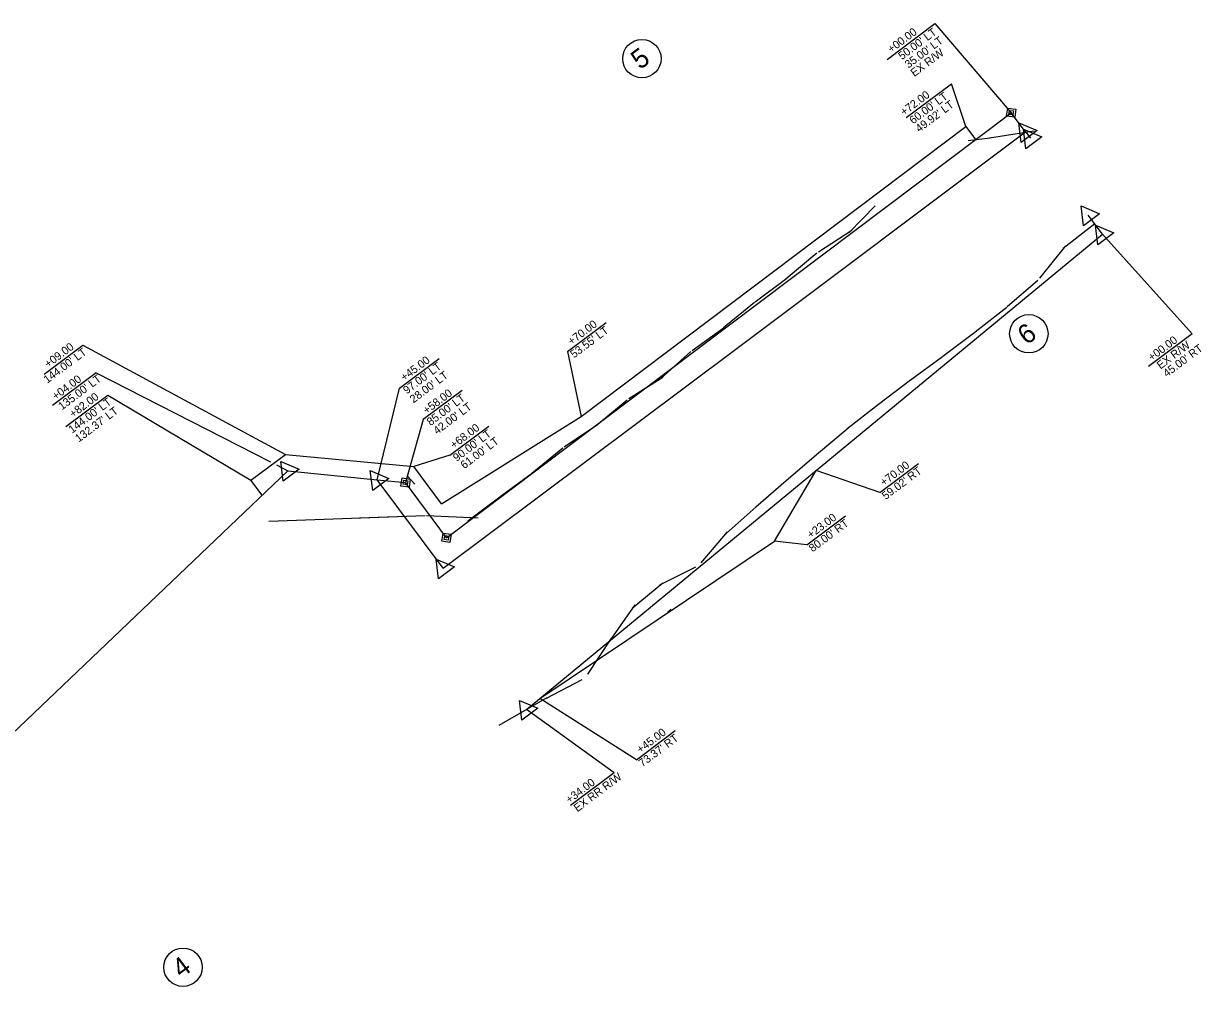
# Model space of a CAD drawing. Extents: x 2187066 to 2190381, y 630308 to 634921.
# Drawn here: x 2187609 to 2188345, y 630712 to 631314 of the extents above; entities that cross this region are included whole.
import ezdxf

# ---------------------------------------------------------------- set-up
doc = ezdxf.new("R2010")
doc.units = 0
for name, color, linetype in [('Default', 7, 'Continuous'), ('Old_Level_1', 7, 'Continuous'), ('Prop Dimension', 7, 'Continuous'), ('Prop Dimension Text', 7, 'Continuous'), ('Prop Guardrail', 7, 'Continuous'), ('Prop Guardrail Anchor Unit CELL', 7, 'Continuous'), ('Prop Horizontal Alignment', 7, 'Continuous'), ('Prop Horizontal Alignment Curve and Spiral Data', 7, 'Continuous'), ('Prop Horizontal Alignment Tick Large', 7, 'Continuous'), ('Prop Horizontal Alignment Tick Small', 7, 'Continuous'), ('Prop Lane Lines', 7, 'Continuous'), ('Prop Paved Shoulder', 7, 'Continuous'), ('Raster_Level_3', 7, 'Continuous'), ('Scratch_Level_3', 7, 'Continuous')]:
    doc.layers.add(name, color=color, linetype=linetype)

msp = doc.modelspace()

# ---------------------------------------------------------------- linework, layer by layer
at = {"layer": 'Default'}
msp.add_line((2187853.68, 631025.69), (2187849, 631030.96), dxfattribs=at)
at = {"layer": 'Old_Level_1'}
for p, q in [((2188053.44, 631109.47), (2188235.45, 631245.82)), ((2188235.45, 631245.82), (2188238.45, 631241.82)), ((2188283.44, 631181.81), (2188274.44, 631193.81)), ((2187923.54, 630884.86), (2188283.44, 631181.81)), ((2187871.43, 630973.13), (2188053.44, 631109.47)), ((2187467.92, 630741.67), (2187774.33, 631034.12)), ((2187774.33, 631034.12), (2187830.23, 631028.48)), ((2187871.43, 630973.13), (2187830.23, 631028.48))]:
    msp.add_line(p, q, dxfattribs=at)
at = {"layer": 'Prop Dimension Text'}
for p, q in [((2188226.45, 631257.82), (2188226.45, 631257.82)), ((2187847.95, 631026.69), (2187847.95, 631026.69)), ((2187873.51, 630992.22), (2187873.51, 630992.22))]:
    msp.add_line(p, q, dxfattribs=at)
for points in [[(2188224.29, 631260.7), (2188229.33, 631259.98), (2188228.61, 631254.94), (2188223.57, 631255.66)], [(2188225.37, 631259.26), (2188227.89, 631258.9), (2188227.53, 631256.38), (2188225.01, 631256.74)], [(2187850.1, 631023.81), (2187845.06, 631024.53), (2187845.79, 631029.57), (2187850.83, 631028.85)], [(2187849.02, 631025.25), (2187846.51, 631025.61), (2187846.87, 631028.13), (2187849.39, 631027.77)], [(2187871.36, 630995.1), (2187876.4, 630994.38), (2187875.67, 630989.34), (2187870.63, 630990.06)], [(2187872.43, 630993.66), (2187874.95, 630993.3), (2187874.59, 630990.78), (2187872.07, 630991.14)]]:
    msp.add_lwpolyline(points, close=True, dxfattribs=at)
at = {"layer": 'Prop Guardrail'}
for p, q in [((2187883.24, 631084.23), (2187858.96, 631066.02)), ((2187858.96, 631066.02), (2187847.95, 631026.69))]:
    msp.add_line(p, q, dxfattribs=at)
at = {"layer": 'Prop Guardrail Anchor Unit CELL'}
for p, q in [((2187873.56, 630992.15), (2188226.45, 631257.82)), ((2188235.45, 631245.82), (2188226.45, 631257.82)), ((2187830.23, 631028.48), (2187847.95, 631026.69)), ((2187873.56, 630992.15), (2187847.95, 631026.69))]:
    msp.add_line(p, q, dxfattribs=at)
at = {"layer": 'Prop Horizontal Alignment'}
for p, q in [((2188148.95, 631291.12), (2188178.81, 631313.5)), ((2188178.81, 631313.5), (2188226.45, 631257.82)), ((2188339.49, 631119.67), (2188283.44, 631181.81)), ((2188339.49, 631119.67), (2188312.17, 631099.18)), ((2187844.19, 631085.72), (2187868.88, 631104.23)), ((2187654.53, 631095.3), (2187627.2, 631074.81)), ((2187654.53, 631095.3), (2187763.63, 631039.59)), ((2187830.23, 631028.48), (2187844.19, 631085.72)), ((2187767.19, 631037.77), (2187774.33, 631034.12)), ((2187978.31, 630845.34), (2187923.54, 630884.86)), ((2187978.31, 630845.34), (2187950.98, 630824.86))]:
    msp.add_line(p, q, dxfattribs=at)
at = {"layer": 'Prop Horizontal Alignment Curve and Spiral Data'}
for p, q in [((2188212.97, 631242.14), (2188240.87, 631246.44)), ((2188199.47, 631240.44), (2188213.24, 631242.18)), ((2188125.15, 631183.04), (2188141.33, 631199.58)), ((2188258.95, 631173.09), (2188278.64, 631188.62)), ((2188105.97, 631170.86), (2188126.85, 631184.43)), ((2188244.33, 631154.44), (2188260.56, 631174.68)), ((2188085.87, 631154.17), (2188105.01, 631170.15)), ((2188066.34, 631139.7), (2188086.32, 631154.52)), ((2188224.01, 631136.67), (2188243.07, 631153.13)), ((2188046.69, 631123.51), (2188065.94, 631139.38)), ((2188203.85, 631120.87), (2188223.64, 631136.36)), ((2188027.01, 631109.17), (2188047.16, 631123.87)), ((2188183.74, 631105.58), (2188203.74, 631120.78)), ((2188007.41, 631091.65), (2188026.23, 631108.53)), ((2188163.25, 631090.68), (2188183.57, 631105.46)), ((2187987.49, 631079.23), (2188008.75, 631092.66)), ((2188143.42, 631075.61), (2188163.42, 631090.81)), ((2187967.06, 631062.45), (2187986.45, 631078.48)), ((2188123.76, 631060.18), (2188143.54, 631075.7)), ((2187947.02, 631048.95), (2187967.82, 631063.02)), ((2188104.69, 631044.19), (2188124.01, 631060.38)), ((2187926.8, 631032.56), (2187946.31, 631048.42)), ((2188085.68, 631027.86), (2188104.78, 631044.27)), ((2187906.97, 631017.95), (2187927.17, 631032.85)), ((2188066.87, 631011.51), (2188085.73, 631027.9)), ((2187886.84, 631002.75), (2187906.88, 631017.88)), ((2188048.28, 630994.97), (2188066.96, 631011.58)), ((2187762.54, 631002.64), (2187860.19, 631006.16)), ((2187819.14, 631004.68), (2187860.19, 631006.16)), ((2187860.99, 631006.16), (2187893.3, 631004.76)), ((2187860.99, 631006.16), (2187893.3, 631004.76)), ((2188032.58, 630976.52), (2188049.22, 630995.93)), ((2188006.94, 630962.84), (2188029.45, 630974.08)), ((2187989.56, 630948.29), (2188008.81, 630964.05)), ((2187976.38, 630928.8), (2187991.42, 630950.29)), ((2187961.94, 630907), (2187976.52, 630929.02)), ((2187935.93, 630892.08), (2187958.21, 630903.65)), ((2187936.33, 630892.3), (2187906.25, 630874.9))]:
    msp.add_line(p, q, dxfattribs=at)
at = {"layer": 'Prop Horizontal Alignment Tick Large'}
msp.add_line((2188011.86, 630945.95), (2188013.93, 630947.52), dxfattribs=at)
at = {"layer": 'Prop Horizontal Alignment Tick Small'}
for p, q in [((2188160.79, 631254.71), (2188189.05, 631275.9)), ((2188198.17, 631249.16), (2188189.05, 631275.9)), ((2187949.07, 631108.53), (2187973.36, 631126.74)), ((2187622.07, 631094.4), (2187646.35, 631112.61)), ((2187646.35, 631112.61), (2187772.94, 631044.33)), ((2187949.07, 631108.53), (2187957.72, 631067.96)), ((2187635.59, 631061.65), (2187661.92, 631081.39)), ((2187661.92, 631081.39), (2187751.33, 631028.13)), ((2187875.62, 631043.8), (2187899.9, 631062.01)), ((2187875.62, 631043.8), (2187853.09, 631036.72)), ((2188144.32, 631020.44), (2188104.56, 631034.22)), ((2188144.32, 631020.44), (2188168.6, 631038.64)), ((2188098.65, 630987.73), (2188122.93, 631005.94)), ((2188098.65, 630987.73), (2188078.43, 630990.09)), ((2187992.17, 630853.52), (2187931.95, 630891.81)), ((2187992.17, 630853.52), (2188016.45, 630871.73))]:
    msp.add_line(p, q, dxfattribs=at)
at = {"layer": 'Prop Lane Lines'}
for p, q in [((2187995.64, 631291.61), (2187995.64, 631291.61)), ((2188237.45, 631119.68), (2188237.45, 631119.68)), ((2187708.84, 630723.87), (2187708.84, 630723.87))]:
    msp.add_line(p, q, dxfattribs=at)
for centre in [(2187995.64, 631291.61), (2188237.45, 631119.68), (2187708.84, 630723.87)]:
    msp.add_circle(centre, 12, dxfattribs=at)
at = {"layer": 'Prop Paved Shoulder'}
msp.add_line((2188235.45, 631245.82), (2188235.45, 631245.82), dxfattribs=at)
msp.add_lwpolyline([(2188232.61, 631239.19), (2188231.13, 631251.58), (2188242.61, 631246.68)], close=True, dxfattribs=at)
at = {"layer": 'Raster_Level_3'}
for p, q in [((2188238.45, 631241.82), (2188238.45, 631241.82)), ((2188274.44, 631193.81), (2188274.44, 631193.81)), ((2188283.44, 631181.81), (2188283.44, 631181.81)), ((2187774.33, 631034.12), (2187774.33, 631034.12)), ((2187830.23, 631028.48), (2187830.23, 631028.48)), ((2187871.43, 630973.13), (2187871.43, 630973.13)), ((2187923.54, 630884.86), (2187923.54, 630884.86))]:
    msp.add_line(p, q, dxfattribs=at)
for points in [[(2188235.61, 631235.19), (2188234.13, 631247.58), (2188245.61, 631242.68)], [(2188271.6, 631187.18), (2188270.12, 631199.57), (2188281.6, 631194.68)], [(2188280.6, 631175.18), (2188279.12, 631187.57), (2188290.6, 631182.68)], [(2187771.49, 631027.5), (2187770.02, 631039.89), (2187781.5, 631034.99)], [(2187827.39, 631021.85), (2187825.91, 631034.24), (2187837.39, 631029.35)], [(2187868.59, 630966.5), (2187867.11, 630978.89), (2187878.59, 630974)], [(2187920.7, 630878.24), (2187919.22, 630890.63), (2187930.7, 630885.73)]]:
    msp.add_lwpolyline(points, close=True, dxfattribs=at)
at = {"layer": 'Scratch_Level_3'}
for p, q in [((2187957.72, 631067.96), (2188198.17, 631249.16)), ((2188198.17, 631249.16), (2188204.2, 631241.07)), ((2187870.34, 631013.41), (2187957.72, 631067.96)), ((2187751.33, 631028.13), (2187772.94, 631044.33)), ((2187772.94, 631044.33), (2187853.09, 631036.72)), ((2187870.34, 631013.41), (2187853.09, 631036.72)), ((2188078.43, 630990.09), (2188104.56, 631034.22)), ((2187758.31, 631018.83), (2187751.33, 631028.13)), ((2187931.95, 630891.81), (2188078.43, 630990.09))]:
    msp.add_line(p, q, dxfattribs=at)

# ---------------------------------------------------------------- texts
at = {"layer": 'Prop Dimension'}
for s, p in [('5', (2187994.5, 631284.35)), ('6', (2188236.14, 631112.29)), ('4', (2187707.78, 630716.67))]:
    msp.add_text(s, height=12, rotation=36.85926, dxfattribs=at).set_placement(p)
at = {"layer": 'Prop Guardrail'}
for s, p in [('+58.00', (2187861.09, 631069.2)), ("85.00' LT", (2187863.56, 631061.95)), ("42.00' LT", (2187867.64, 631056.51))]:
    msp.add_text(s, height=5, rotation=36.85926, dxfattribs=at).set_placement(p)
at = {"layer": 'Prop Horizontal Alignment'}
for s, p in [('+00.00', (2188151.5, 631294.9)), ("50.00' LT", (2188158.18, 631290.56)), ("35.00' LT", (2188162.2, 631285.25)), ('EX R/W', (2188165.87, 631280.04)), ('+00.00', (2188314.3, 631102.36)), ('EX R/W', (2188319.77, 631097.3)), ("45.00' RT", (2188323.69, 631092.32)), ('+45.00', (2187847.14, 631089.8)), ("97.00' LT", (2187848.73, 631081.7)), ('+04.00', (2187629.34, 631077.99)), ("135.00' LT", (2187633.17, 631071.74)), ("28.00' LT", (2187852.91, 631076.13)), ('+34.00', (2187950.33, 630825.94)), ('EX RR R/W', (2187955.35, 630820.67))]:
    msp.add_text(s, height=5, rotation=36.85926, dxfattribs=at).set_placement(p)
at = {"layer": 'Prop Horizontal Alignment Tick Small'}
for s, p in [('+72.00', (2188159.49, 631255.61)), ("60.00' LT", (2188165.12, 631250.42)), ("49.92' LT", (2188168.96, 631245.3)), ('+70.00', (2187951.62, 631112.31)), ("53.55' LT", (2187953.21, 631104.21)), ('+09.00', (2187624.62, 631098.18)), ("144.00' LT", (2187624, 631088.42)), ("144.00' LT", (2187639.56, 631057.2)), ('+82.00', (2187640.18, 631066.96)), ("132.37' LT", (2187643.74, 631051.64)), ('+68.00', (2187878.17, 631047.58)), ("90.00' LT", (2187879.9, 631039.58)), ("61.00' LT", (2187884.62, 631034.98)), ('+70.00', (2188146.87, 631024.22)), ("59.02' RT", (2188148, 631015.74)), ('+23.00', (2188101.2, 630991.51)), ("80.00' RT", (2188102.35, 630983.01)), ('+45.00', (2187994.72, 630857.3)), ("73.37' RT", (2187995.92, 630848.73))]:
    msp.add_text(s, height=5, rotation=36.85926, dxfattribs=at).set_placement(p)

doc.saveas('drawing.dxf')
